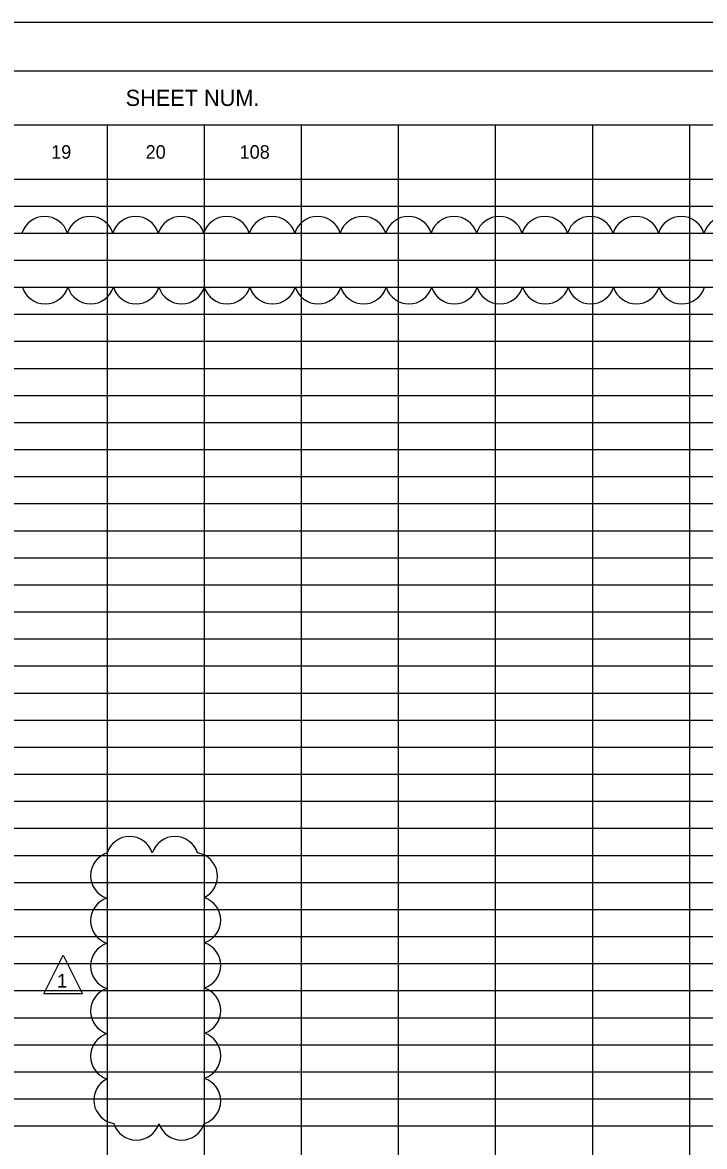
# Model space of a CAD drawing. Extents: x -156 to 77, y 0 to 24.
# Drawn here: x 5.65 to 12.71, y 10.37 to 22 of the extents above; entities that cross this region are included whole.
import ezdxf

# ---------------------------------------------------------------- set-up
doc = ezdxf.new("R2010")
doc.units = 0
for name, color, linetype in [('Default', 7, 'Continuous'), ('MU_Markup_Cloud', 7, 'Continuous'), ('SH_Border', 7, 'Continuous'), ('SH_Cut_Line', 7, 'Continuous')]:
    doc.layers.add(name, color=color, linetype=linetype)

msp = doc.modelspace()

# ---------------------------------------------------------------- linework, layer by layer
at = {"layer": 'Default'}
for p, q in [((1.5, 21.5), (32.004, 21.5)), ((1.5, 20.94), (15.566, 20.94)), ((6.524, 20.94), (6.524, 0.5)), ((7.528, 20.94), (7.528, 0.5)), ((8.533, 20.94), (8.533, 0.5)), ((9.538, 20.94), (9.538, 0.5)), ((10.542, 20.94), (10.542, 0.5)), ((11.547, 20.94), (11.547, 0.5)), ((12.552, 20.94), (12.552, 0.5)), ((1.5, 20.38), (32.004, 20.38)), ((1.5, 20.1), (32.004, 20.1)), ((1.5, 19.82), (32.004, 19.82)), ((1.5, 19.54), (32.004, 19.54)), ((1.5, 19.26), (32.004, 19.26)), ((1.5, 18.98), (32.004, 18.98)), ((1.5, 18.7), (32.004, 18.7)), ((1.5, 18.42), (32.004, 18.42)), ((1.5, 18.14), (32.004, 18.14)), ((1.5, 17.86), (32.004, 17.86)), ((1.5, 17.58), (32.004, 17.58)), ((1.5, 17.3), (32.004, 17.3)), ((1.5, 17.02), (32.004, 17.02)), ((1.5, 16.74), (32.004, 16.74)), ((1.5, 16.46), (32.004, 16.46)), ((1.5, 16.18), (32.004, 16.18)), ((1.5, 15.9), (32.004, 15.9)), ((1.5, 15.62), (32.004, 15.62)), ((1.5, 15.34), (32.004, 15.34)), ((1.5, 15.06), (32.004, 15.06)), ((1.5, 14.78), (32.004, 14.78)), ((1.5, 14.5), (32.004, 14.5)), ((1.5, 14.22), (32.004, 14.22)), ((1.5, 13.94), (32.004, 13.94)), ((1.5, 13.66), (32.004, 13.66)), ((1.5, 13.38), (32.004, 13.38)), ((1.5, 13.1), (32.004, 13.1)), ((1.5, 12.82), (32.004, 12.82)), ((1.5, 12.54), (32.004, 12.54)), ((1.5, 12.26), (32.004, 12.26)), ((1.5, 11.98), (32.004, 11.98)), ((1.5, 11.7), (32.004, 11.7)), ((1.5, 11.42), (32.004, 11.42)), ((1.5, 11.14), (32.004, 11.14)), ((1.5, 10.86), (32.004, 10.86)), ((1.5, 10.58), (32.004, 10.58))]:
    msp.add_line(p, q, dxfattribs=at)
at = {"layer": 'MU_Markup_Cloud'}
msp.add_lwpolyline([(5.868, 11.946), (6.068, 12.346), (6.268, 11.946)], close=True, dxfattribs=at)
for centre, radius, start, end in [((5.877, 19.746), 0.247, 17.5, 162.5), ((6.348, 19.746), 0.247, 17.5, 162.5), ((6.818, 19.746), 0.247, 17.5, 162.5), ((7.289, 19.746), 0.247, 17.5, 162.5), ((7.76, 19.746), 0.247, 17.5, 162.5), ((8.231, 19.746), 0.247, 17.5, 162.5), ((8.701, 19.746), 0.247, 17.5, 162.5), ((9.172, 19.746), 0.247, 17.5, 162.5), ((9.643, 19.746), 0.247, 17.5, 162.5), ((10.114, 19.746), 0.247, 17.5, 162.5), ((10.584, 19.746), 0.247, 17.5, 162.5), ((11.055, 19.746), 0.247, 17.5, 162.5), ((11.526, 19.746), 0.247, 17.5, 162.5), ((11.997, 19.746), 0.247, 17.5, 162.5), ((12.467, 19.746), 0.247, 17.5, 162.5), ((12.938, 19.746), 0.247, 17.5, 162.5), ((5.882, 19.334), 0.247, 197.5, 342.5), ((6.353, 19.334), 0.247, 197.5, 342.5), ((6.824, 19.334), 0.247, 197.5, 342.5), ((7.295, 19.334), 0.247, 197.5, 342.5), ((7.765, 19.334), 0.247, 197.5, 342.5), ((8.236, 19.334), 0.247, 197.5, 342.5), ((8.707, 19.334), 0.247, 197.5, 342.5), ((9.178, 19.334), 0.247, 197.5, 342.5), ((9.648, 19.334), 0.247, 197.5, 342.5), ((10.119, 19.334), 0.247, 197.5, 342.5), ((10.59, 19.334), 0.247, 197.5, 342.5), ((11.061, 19.334), 0.247, 197.5, 342.5), ((11.531, 19.334), 0.247, 197.5, 342.5), ((12.002, 19.334), 0.247, 197.5, 342.5), ((12.473, 19.334), 0.247, 197.5, 342.5), ((6.757, 13.331), 0.245, 17.5, 162.5), ((7.225, 13.331), 0.245, 17.5, 162.5), ((6.597, 13.171), 0.245, 107.5, 252.5), ((7.421, 13.163), 0.245, 296.0626, 81.0626), ((6.597, 12.703), 0.245, 107.5, 252.5), ((7.455, 12.709), 0.245, 287.5, 72.5), ((6.597, 12.236), 0.245, 107.5, 252.5), ((7.455, 12.241), 0.245, 287.5, 72.5), ((6.597, 11.768), 0.245, 107.5, 252.5), ((7.455, 11.773), 0.245, 287.5, 72.5), ((6.597, 11.301), 0.245, 107.5, 252.5), ((7.455, 11.306), 0.245, 287.5, 72.5), ((6.631, 10.847), 0.245, 116.0626, 261.0626), ((7.455, 10.838), 0.245, 287.5, 72.5), ((6.827, 10.678), 0.245, 197.5, 342.5), ((7.294, 10.678), 0.245, 197.5, 342.5)]:
    msp.add_arc(centre, radius, start, end, dxfattribs=at)
at = {"layer": 'SH_Border'}
msp.add_lwpolyline([(1.5, 21.5), (33.5, 21.5), (33.5, 0.5), (1.5, 0.5)], close=True, dxfattribs=at)
at = {"layer": 'SH_Cut_Line'}
msp.add_lwpolyline([(0, 0), (34, 0), (34, 22), (0, 22)], close=True, dxfattribs=at)

# ---------------------------------------------------------------- texts
at = {"layer": 'Default'}
for s, height, p in [('SHEET NUM.', 0.168, (6.715, 21.136)), ('19', 0.14, (5.944, 20.59)), ('20', 0.14, (6.922, 20.59)), ('108', 0.14, (7.895, 20.59))]:
    msp.add_text(s, height=height, dxfattribs=at).set_placement(p)
at = {"layer": 'MU_Markup_Cloud'}
msp.add_text('1', height=0.14, dxfattribs=at).set_placement((6.005, 12.012))

doc.saveas('drawing.dxf')
